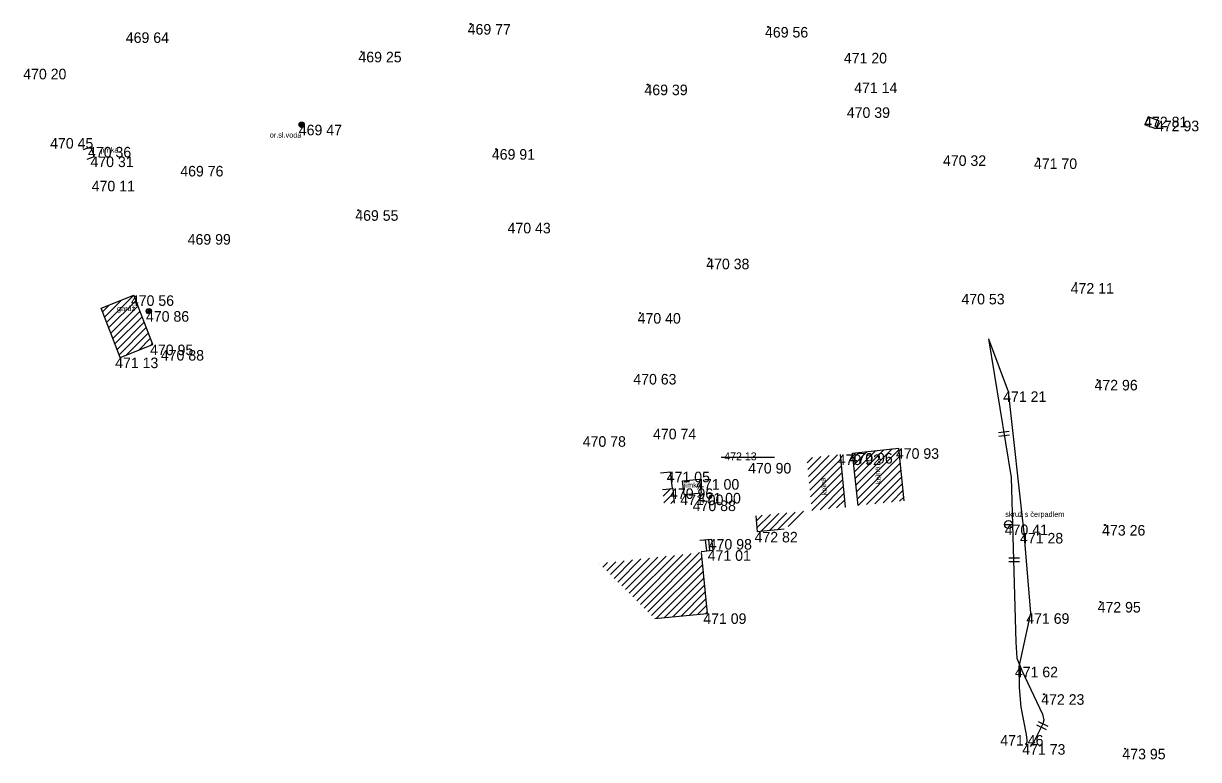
# Model space of a CAD drawing. Extents: x -553731 to -553573, y -1076100 to -1075378.
# Drawn here: x -553701.3 to -553590, y -1075843.9 to -1075774.2 of the extents above; entities that cross this region are included whole.
import ezdxf

# ---------------------------------------------------------------- set-up
doc = ezdxf.new("R2010")
doc.units = 0
for name, color, linetype in [('1', 7, 'Continuous'), ('14', 7, 'Continuous'), ('18', 7, 'Continuous'), ('20', 7, 'Continuous'), ('27', 7, 'Continuous'), ('32', 7, 'Continuous'), ('52', 7, 'Continuous'), ('6', 7, 'Continuous'), ('62', 7, 'Continuous')]:
    doc.layers.add(name, color=color, linetype=linetype)

# ---------------------------------------------------------------- blocks, each defined once
blk = doc.blocks.new('POINT_DISPLAY')
blk.add_line((0, 0), (0, 0))
blk = doc.blocks.new('SLB')
at = {"layer": '20'}
for radius in [0.25, 0.158, 0.05]:
    blk.add_circle((0, 0), radius, dxfattribs=at)
blk = doc.blocks.new('T')
at = {"layer": '6'}
blk.add_circle((0, 0), 0.05, dxfattribs=at)
blk = doc.blocks.new('ST')
at = {"layer": '1'}
blk.add_line((-0.375, 0), (0.375, 0), dxfattribs=at)
blk.add_circle((0, 0), 0.375, dxfattribs=at)
blk = doc.blocks.new('OSV')
at = {"layer": '1'}
for radius in [0.25, 0.158, 0.05]:
    blk.add_circle((0, 0), radius, dxfattribs=at)
blk = doc.blocks.new('ROV')
at = {"layer": '62'}
for p, q in [((-0.348, -0.51), (-0.348, 0.51)), ((0, -0.51), (0, 0.51))]:
    blk.add_line(p, q, dxfattribs=at)

msp = doc.modelspace()

# ---------------------------------------------------------------- linework, layer by layer
at = {"layer": '14'}
for p, q in [((-553693.98, -1075801.18), (-553690.88, -1075799.95)), ((-553689.06, -1075804.62), (-553690.88, -1075799.95)), ((-553692.16, -1075805.85), (-553693.98, -1075801.18)), ((-553692.16, -1075805.85), (-553689.06, -1075804.62)), ((-553623.46, -1075820.01), (-553623.91, -1075815.03)), ((-553622.77, -1075814.89), (-553618.4, -1075814.44)), ((-553622.26, -1075819.86), (-553622.77, -1075814.89)), ((-553617.89, -1075819.41), (-553618.4, -1075814.44)), ((-553640.79, -1075818.35), (-553639.78, -1075818.24)), ((-553639.63, -1075819.64), (-553639.78, -1075818.24)), ((-553631.95, -1075820.84), (-553631.8, -1075822.36)), ((-553629.24, -1075822.11), (-553631.8, -1075822.36)), ((-553637.11, -1075824.31), (-553636.54, -1075830.08)), ((-553641.52, -1075830.57), (-553636.54, -1075830.08))]:
    msp.add_line(p, q, dxfattribs=at)
at = {"layer": '18'}
for p, q in [((-553594.78, -1075783.03), (-553595.07, -1075783.8)), ((-553593.76, -1075783.41), (-553594.78, -1075783.03)), ((-553594.05, -1075784.18), (-553595.07, -1075783.8)), ((-553593.76, -1075783.41), (-553594.05, -1075784.18)), ((-553695.63, -1075786.15), (-553694.94, -1075785.89)), ((-553694.61, -1075786.8), (-553694.94, -1075785.89)), ((-553695.29, -1075787.06), (-553694.61, -1075786.8)), ((-553640.96, -1075816.76), (-553640.01, -1075816.66)), ((-553639.84, -1075818.25), (-553640.01, -1075816.66)), ((-553638.88, -1075817.52), (-553637.23, -1075817.36)), ((-553638.73, -1075818.83), (-553638.88, -1075817.52)), ((-553637.08, -1075818.67), (-553637.23, -1075817.36)), ((-553638.73, -1075818.83), (-553637.08, -1075818.67)), ((-553637.24, -1075823.16), (-553636.13, -1075823.04)), ((-553636.73, -1075823.1), (-553636.62, -1075824.16)), ((-553636.43, -1075823.07), (-553636.32, -1075824.13)), ((-553636.13, -1075823.04), (-553636.02, -1075824.1)), ((-553637.12, -1075824.22), (-553636.02, -1075824.1))]:
    msp.add_line(p, q, dxfattribs=at)
at = {"layer": '27'}
for p, q in [((-553609.89, -1075804.08), (-553608.03, -1075809.05)), ((-553608.03, -1075809.05), (-553606.54, -1075822.46)), ((-553606.54, -1075822.46), (-553605.93, -1075830.07)), ((-553605.93, -1075830.07), (-553607.02, -1075835.14))]:
    msp.add_line(p, q, dxfattribs=at)
msp.add_lwpolyline([(-553607.02, -1075835.14), (-553607, -1075837.1), (-553606.83, -1075838.97), (-553606.33, -1075841.56), (-553606.27, -1075842.08), (-553606.28, -1075842.28), (-553606.33, -1075842.47)], dxfattribs=at)
at = {"layer": '32'}
for p, q in [((-553693.85, -1075801.51), (-553693.22, -1075800.88)), ((-553693.65, -1075802.02), (-553692.05, -1075800.42)), ((-553693.46, -1075802.53), (-553690.88, -1075799.95)), ((-553693.26, -1075803.03), (-553690.68, -1075800.46)), ((-553693.06, -1075803.54), (-553690.48, -1075800.97)), ((-553692.86, -1075804.05), (-553690.29, -1075801.48)), ((-553692.66, -1075804.56), (-553690.09, -1075801.99)), ((-553692.46, -1075805.07), (-553689.89, -1075802.49)), ((-553692.27, -1075805.58), (-553689.69, -1075803)), ((-553691.61, -1075805.63), (-553689.49, -1075803.51)), ((-553690.44, -1075805.17), (-553689.29, -1075804.02)), ((-553689.27, -1075804.7), (-553689.09, -1075804.53)), ((-553627.08, -1075815.81), (-553626.57, -1075815.3)), ((-553627.02, -1075816.46), (-553625.78, -1075815.22)), ((-553626.96, -1075817.11), (-553624.99, -1075815.14)), ((-553626.89, -1075817.75), (-553624.2, -1075815.06)), ((-553626.83, -1075818.4), (-553623.87, -1075815.44)), ((-553622.72, -1075815.38), (-553622.17, -1075814.83)), ((-553622.65, -1075816.02), (-553621.38, -1075814.75)), ((-553622.59, -1075816.66), (-553620.6, -1075814.67)), ((-553622.52, -1075817.3), (-553619.81, -1075814.58)), ((-553622.46, -1075817.94), (-553619.02, -1075814.5)), ((-553622.39, -1075818.58), (-553618.39, -1075814.58)), ((-553622.32, -1075819.22), (-553618.32, -1075815.22)), ((-553626.77, -1075819.05), (-553623.82, -1075816.09)), ((-553622.26, -1075819.86), (-553618.25, -1075815.86)), ((-553621.47, -1075819.78), (-553618.19, -1075816.5)), ((-553626.71, -1075819.69), (-553623.76, -1075816.74)), ((-553626.65, -1075820.34), (-553623.7, -1075817.39)), ((-553620.68, -1075819.7), (-553618.12, -1075817.14)), ((-553640.72, -1075818.99), (-553640, -1075818.26)), ((-553640.65, -1075819.62), (-553639.73, -1075818.7)), ((-553625.86, -1075820.26), (-553623.64, -1075818.04)), ((-553625.07, -1075820.18), (-553623.58, -1075818.68)), ((-553619.89, -1075819.62), (-553618.06, -1075817.78)), ((-553619.1, -1075819.54), (-553617.99, -1075818.42)), ((-553640, -1075819.68), (-553639.66, -1075819.34)), ((-553624.29, -1075820.09), (-553623.52, -1075819.33)), ((-553618.32, -1075819.46), (-553617.92, -1075819.06)), ((-553631.9, -1075821.34), (-553631.34, -1075820.78)), ((-553631.84, -1075821.99), (-553630.55, -1075820.71)), ((-553631.47, -1075822.33), (-553629.77, -1075820.63)), ((-553630.68, -1075822.25), (-553628.99, -1075820.56)), ((-553629.9, -1075822.17), (-553628.21, -1075820.49)), ((-553628.88, -1075821.86), (-553627.43, -1075820.41)), ((-553623.5, -1075820.01), (-553623.47, -1075819.98)), ((-553642.52, -1075829.58), (-553637.27, -1075824.33)), ((-553646.43, -1075825.71), (-553645.99, -1075825.27)), ((-553646.07, -1075826.06), (-553645.2, -1075825.19)), ((-553645.72, -1075826.41), (-553644.41, -1075825.1)), ((-553645.36, -1075826.77), (-553643.61, -1075825.02)), ((-553645.01, -1075827.12), (-553642.82, -1075824.93)), ((-553644.65, -1075827.47), (-553642.03, -1075824.85)), ((-553644.3, -1075827.82), (-553641.23, -1075824.76)), ((-553643.94, -1075828.17), (-553640.44, -1075824.67)), ((-553643.59, -1075828.53), (-553639.65, -1075824.59)), ((-553643.23, -1075828.88), (-553638.86, -1075824.5)), ((-553642.88, -1075829.23), (-553638.06, -1075824.42)), ((-553642.16, -1075829.93), (-553637.06, -1075824.83)), ((-553641.81, -1075830.28), (-553637, -1075825.47)), ((-553641.38, -1075830.56), (-553636.93, -1075826.12)), ((-553640.59, -1075830.48), (-553636.87, -1075826.76)), ((-553639.81, -1075830.4), (-553636.81, -1075827.4)), ((-553639.02, -1075830.33), (-553636.74, -1075828.05)), ((-553638.24, -1075830.25), (-553636.68, -1075828.69)), ((-553637.45, -1075830.17), (-553636.61, -1075829.33)), ((-553636.67, -1075830.09), (-553636.55, -1075829.98))]:
    msp.add_line(p, q, dxfattribs=at)
at = {"layer": '62'}
for p, q in [((-553609.89, -1075804.08), (-553607.75, -1075817.2)), ((-553635.24, -1075815.27), (-553630.16, -1075815.27)), ((-553607.75, -1075817.2), (-553607.3, -1075832.82)), ((-553607.3, -1075832.82), (-553607.2, -1075834.34)), ((-553607.2, -1075834.34), (-553606.75, -1075835.5)), ((-553606.75, -1075835.5), (-553604.77, -1075839.62)), ((-553604.77, -1075839.62), (-553604.65, -1075840.2)), ((-553604.74, -1075840.56), (-553605.61, -1075842.25)), ((-553604.65, -1075840.2), (-553604.74, -1075840.56)), ((-553605.61, -1075842.25), (-553605.96, -1075842.68))]:
    msp.add_line(p, q, dxfattribs=at)

# ---------------------------------------------------------------- block references
at = {"layer": '1'}
for name, p in [('POINT_DISPLAY', (-553658.96, -1075774.25)), ('POINT_DISPLAY', (-553691.34, -1075775.04)), ('POINT_DISPLAY', (-553630.77, -1075774.53)), ('POINT_DISPLAY', (-553669.3, -1075776.88)), ('POINT_DISPLAY', (-553623.23, -1075776.98)), ('POINT_DISPLAY', (-553701.09, -1075778.49)), ('POINT_DISPLAY', (-553622.15, -1075779.79)), ('POINT_DISPLAY', (-553642.19, -1075779.99)), ('POINT_DISPLAY', (-553623.05, -1075782.14)), ('POINT_DISPLAY', (-553594.78, -1075783.03)), ('OSV', (-553674.97, -1075783.79)), ('POINT_DISPLAY', (-553674.97, -1075783.79)), ('POINT_DISPLAY', (-553593.76, -1075783.41)), ('POINT_DISPLAY', (-553698.55, -1075785.05)), ('POINT_DISPLAY', (-553694.94, -1075785.89)), ('POINT_DISPLAY', (-553656.55, -1075786.1)), ('POINT_DISPLAY', (-553694.61, -1075786.8)), ('POINT_DISPLAY', (-553613.95, -1075786.69)), ('POINT_DISPLAY', (-553605.22, -1075786.98)), ('POINT_DISPLAY', (-553686.17, -1075787.69)), ('POINT_DISPLAY', (-553694.38, -1075789.1)), ('POINT_DISPLAY', (-553669.6, -1075791.89)), ('POINT_DISPLAY', (-553655.21, -1075793.08)), ('POINT_DISPLAY', (-553685.46, -1075794.15)), ('POINT_DISPLAY', (-553636.38, -1075796.48)), ('POINT_DISPLAY', (-553601.63, -1075798.79)), ('POINT_DISPLAY', (-553612.2, -1075799.81)), ('POINT_DISPLAY', (-553690.88, -1075799.95)), ('POINT_DISPLAY', (-553689.45, -1075801.45)), ('POINT_DISPLAY', (-553642.89, -1075801.63)), ('POINT_DISPLAY', (-553689.06, -1075804.62)), ('POINT_DISPLAY', (-553688.05, -1075805.13)), ('POINT_DISPLAY', (-553692.16, -1075805.85)), ('POINT_DISPLAY', (-553643.28, -1075807.4)), ('POINT_DISPLAY', (-553599.57, -1075807.96)), ('POINT_DISPLAY', (-553608.03, -1075809.05)), ('POINT_DISPLAY', (-553641.43, -1075812.59)), ('POINT_DISPLAY', (-553648.08, -1075813.3)), ('POINT_DISPLAY', (-553623.91, -1075815.03)), ('POINT_DISPLAY', (-553622.77, -1075814.89)), ('POINT_DISPLAY', (-553618.4, -1075814.44)), ('POINT_DISPLAY', (-553632.39, -1075815.83)), ('POINT_DISPLAY', (-553640.01, -1075816.66)), ('POINT_DISPLAY', (-553637.23, -1075817.36)), ('POINT_DISPLAY', (-553639.78, -1075818.24)), ('POINT_DISPLAY', (-553638.73, -1075818.83)), ('POINT_DISPLAY', (-553637.08, -1075818.67)), ('POINT_DISPLAY', (-553637.66, -1075819.39)), ('ST', (-553608, -1075821.67)), ('POINT_DISPLAY', (-553608, -1075821.67)), ('POINT_DISPLAY', (-553598.86, -1075821.71)), ('POINT_DISPLAY', (-553636.13, -1075823.04)), ('POINT_DISPLAY', (-553631.8, -1075822.36)), ('POINT_DISPLAY', (-553606.54, -1075822.46)), ('POINT_DISPLAY', (-553636.02, -1075824.1)), ('POINT_DISPLAY', (-553599.29, -1075829)), ('POINT_DISPLAY', (-553636.54, -1075830.08)), ('POINT_DISPLAY', (-553605.93, -1075830.07)), ('POINT_DISPLAY', (-553607.02, -1075835.14)), ('POINT_DISPLAY', (-553604.64, -1075837.74)), ('POINT_DISPLAY', (-553608.41, -1075841.61)), ('POINT_DISPLAY', (-553606.33, -1075842.47)), ('POINT_DISPLAY', (-553596.94, -1075842.91))]:
    msp.add_blockref(name, p, dxfattribs=at)
at = {"layer": '20'}
msp.add_blockref('SLB', (-553689.45, -1075801.45), dxfattribs=at)
at = {"layer": '32'}
for p in [(-553690.88, -1075799.95), (-553640.79, -1075818.35), (-553622.26, -1075819.86), (-553626.65, -1075820.34), (-553646.78, -1075825.36)]:
    msp.add_blockref('POINT_DISPLAY', p, dxfattribs=at)
at = {"layer": '6'}
for p in [(-553658.96, -1075774.25), (-553630.77, -1075774.53), (-553669.3, -1075776.88), (-553642.19, -1075779.99), (-553656.55, -1075786.1), (-553605.22, -1075786.98), (-553669.6, -1075791.89), (-553636.38, -1075796.48), (-553601.63, -1075798.79), (-553642.89, -1075801.63), (-553599.57, -1075807.96), (-553598.86, -1075821.71), (-553599.29, -1075829), (-553604.64, -1075837.74), (-553606.33, -1075842.47), (-553596.94, -1075842.91)]:
    msp.add_blockref('T', p, dxfattribs=at)
at = {"layer": '62'}
for p, xscale, yscale, rotation in [((-553608.4, -1075813.23), 0.9999989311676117, 0.9999989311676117, -82.00218589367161), ((-553607.47, -1075825.17), 0.9999968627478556, 0.9999968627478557, -89.23131013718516), ((-553604.9, -1075840.86), 1.0000027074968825, 1.0000027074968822, -117.02431251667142)]:
    msp.add_blockref('ROV', p, dxfattribs=dict(at, xscale=xscale, yscale=yscale, rotation=rotation))

# ---------------------------------------------------------------- texts
at = {"layer": '52'}
for s, p in [('or.sl.voda', (-553677.99, -1075785.01)), ('jímka', (-553693.98, -1075786.43)), ('garáž', (-553692.46, -1075801.44)), ('jímky', (-553638.8, -1075818.18)), ('skruž s čerpadlem', (-553608.31, -1075820.94))]:
    msp.add_text(s, height=0.5, dxfattribs=at).set_placement(p)
for rotation, p in [(96, (-553620.05, -1075817.81)), (96.4973, (-553625.17, -1075818.86))]:
    msp.add_text('kolna', height=0.5, rotation=rotation, dxfattribs=at).set_placement(p)
at = {"layer": '6'}
for s, p in [('469 77 ', (-553659.24, -1075775.25)), ('469 64 ', (-553691.63, -1075776.04)), ('469 56 ', (-553631.07, -1075775.53)), ('469 25 ', (-553669.59, -1075777.88)), ('471 20 ', (-553623.6, -1075777.98)), ('470 20 ', (-553701.35, -1075779.49)), ('471 14 ', (-553622.62, -1075780.79)), ('469 39 ', (-553642.49, -1075780.99)), ('470 39 ', (-553623.32, -1075783.14)), ('472 81 ', (-553595.15, -1075784.03)), ('469 47 ', (-553675.24, -1075784.79)), ('472 93 ', (-553594.03, -1075784.41)), ('470 45 ', (-553698.8, -1075786.05)), ('470 36 ', (-553695.21, -1075786.89)), ('469 91 ', (-553656.95, -1075787.1)), ('470 31 ', (-553694.98, -1075787.8)), ('470 32 ', (-553614.21, -1075787.69)), ('471 70 ', (-553605.59, -1075787.98)), ('469 76 ', (-553686.47, -1075788.69)), ('470 11 ', (-553694.86, -1075790.1)), ('469 55 ', (-553669.89, -1075792.89)), ('470 43 ', (-553655.46, -1075794.08)), ('469 99 ', (-553685.77, -1075795.15)), ('470 38 ', (-553636.64, -1075797.48)), ('472 11 ', (-553602.11, -1075799.79)), ('470 53 ', (-553612.46, -1075800.81)), ('470 56 ', (-553691.15, -1075800.95)), ('470 86 ', (-553689.72, -1075802.45)), ('470 40 ', (-553643.14, -1075802.63)), ('470 95 ', (-553689.33, -1075805.62)), ('470 88 ', (-553688.31, -1075806.13)), ('471 13 ', (-553692.64, -1075806.85)), ('470 63 ', (-553643.55, -1075808.4)), ('472 96 ', (-553599.85, -1075808.96)), ('471 21 ', (-553608.51, -1075810.05)), ('470 74 ', (-553641.68, -1075813.59)), ('470 78 ', (-553648.34, -1075814.3)), ('470 92 ', (-553624.18, -1075816.03)), ('470 96 ', (-553623.06, -1075815.89)), ('470 93 ', (-553618.67, -1075815.44)), ('470 90 ', (-553632.67, -1075816.83)), ('471 05 ', (-553640.38, -1075817.66)), ('471 00 ', (-553637.6, -1075818.36)), ('470 96 ', (-553640.07, -1075819.24)), ('471 00 ', (-553639.1, -1075819.83)), ('471 00 ', (-553637.45, -1075819.67)), ('470 88 ', (-553637.92, -1075820.39)), ('470 41 ', (-553608.36, -1075822.67)), ('473 26 ', (-553599.13, -1075822.71)), ('470 98 ', (-553636.4, -1075824.04)), ('472 82 ', (-553632.06, -1075823.36)), ('471 28 ', (-553606.91, -1075823.46)), ('471 01 ', (-553636.5, -1075825.1)), ('472 95 ', (-553599.56, -1075830)), ('471 09 ', (-553636.92, -1075831.08)), ('471 69 ', (-553606.32, -1075831.07)), ('471 62 ', (-553607.4, -1075836.14)), ('472 23 ', (-553604.9, -1075838.74)), ('471 46 ', (-553608.78, -1075842.61)), ('471 73 ', (-553606.7, -1075843.47)), ('473 95 ', (-553597.21, -1075843.91))]:
    msp.add_text(s, height=1, dxfattribs=at).set_placement(p)
at = {"layer": '62'}
msp.add_text('472 13', height=0.75, dxfattribs=at).set_placement((-553634.93, -1075815.58))

doc.saveas('drawing.dxf')
